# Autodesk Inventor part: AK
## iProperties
Created: 2004-01
Part Number: AK
Material: Standard
Document SubType Name: Modellieren
Designer: Ulrich
Control State: 0
Master: False
Checked Out: False
Shininess: 20.0
Angle Display Precision: 2
Document Length Units: 11269
Document Angle Units: 11279
Document Time Units: 11290
Document Mass Units: 11283
Document Length Units Precision: 3
Document Angle Units Precision: 2
Density: 0.0
Volumn: 0.0
Area: 0.0
PropertySet Name: Model Information
Author: Ulrich
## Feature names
1. Grundkörper [Extrusion]
2. Ausfräsung [Extrusion]
3. Ausfräsung_Rundung [Fillet]
4. Bohrung [Extrusion]
